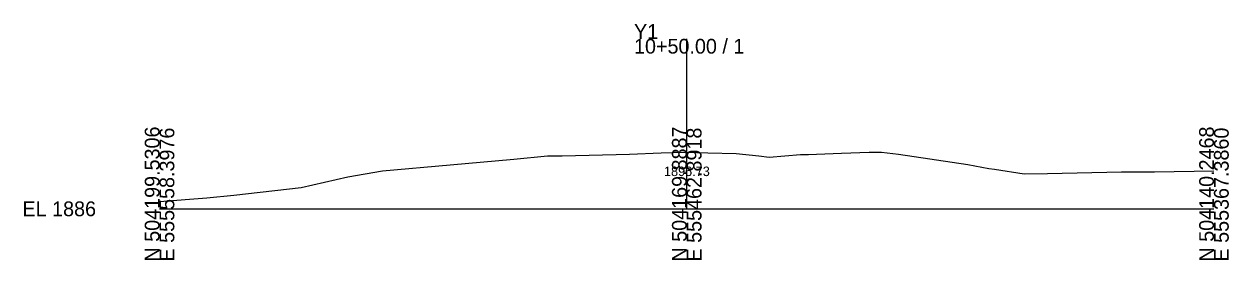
# Model space of a CAD drawing. Extents: x -26 to 1503, y -10 to 5015.
# Drawn here: x -25.7 to 202.8, y 490.3 to 535 of the extents above; entities that cross this region are included whole.
import ezdxf

# ---------------------------------------------------------------- set-up
doc = ezdxf.new("R2010")
doc.units = 0
for name, color, linetype in [('Default', 7, 'Continuous'), ('Exist Cross Section Cell', 7, 'Continuous'), ('Exist XS Center Line Elevation Label', 7, 'Continuous'), ('Exist XS Ground Line', 7, 'Continuous')]:
    doc.layers.add(name, color=color, linetype=linetype)

msp = doc.modelspace()

# ---------------------------------------------------------------- linework, layer by layer
at = {"layer": 'Exist Cross Section Cell'}
for p, q in [((100, 500), (100, 532.24)), ((0, 500), (100, 500)), ((100, 500), (200, 500))]:
    msp.add_line(p, q, dxfattribs=at)
at = {"layer": 'Exist XS Ground Line'}
for p, q in [((67.2, 509.39), (73.61, 510.05)), ((73.61, 510.05), (76.39, 510.05)), ((76.39, 510.05), (89.12, 510.37)), ((89.12, 510.37), (95.17, 510.6)), ((95.17, 510.6), (99.71, 510.74)), ((99.71, 510.74), (104.02, 510.61)), ((104.02, 510.61), (109.37, 510.46)), ((109.37, 510.46), (113.67, 510.08)), ((113.67, 510.08), (115.65, 509.8)), ((115.65, 509.8), (121.57, 510.32)), ((121.57, 510.32), (122.33, 510.32)), ((122.33, 510.32), (123.12, 510.33)), ((123.12, 510.33), (124.6, 510.37)), ((124.6, 510.37), (129.37, 510.55)), ((129.37, 510.55), (134.59, 510.72)), ((134.59, 510.72), (136.92, 510.75)), ((136.92, 510.75), (140.15, 510.37)), ((140.15, 510.37), (153.34, 508.38)), ((42.26, 507.2), (55.14, 508.34)), ((55.14, 508.34), (67.2, 509.39)), ((153.34, 508.38), (157.28, 507.66)), ((157.28, 507.66), (158.36, 507.52)), ((158.36, 507.52), (164.01, 506.66)), ((26.85, 504.05), (35.74, 506.06)), ((35.74, 506.06), (42.26, 507.2)), ((164.01, 506.66), (168.46, 506.69)), ((168.46, 506.69), (182.49, 507.04)), ((182.49, 507.04), (188.7, 507.01)), ((188.7, 507.01), (200, 507.22)), ((14.09, 502.58), (26.85, 504.05)), ((0, 501.41), (8.94, 502.1)), ((8.94, 502.1), (14.09, 502.58))]:
    msp.add_line(p, q, dxfattribs=at)

# ---------------------------------------------------------------- texts
at = {"layer": 'Default'}
msp.add_text('-', height=0.0001, dxfattribs=at).set_placement((0, 500))
at = {"layer": 'Exist Cross Section Cell'}
for s, p in [('Y1', (90, 532.24)), ('10+50.00 / 1', (90, 529.44)), ('EL 1886', (-26, 498.6))]:
    msp.add_text(s, height=2.8, dxfattribs=at).set_placement(p)
for s, p in [('N 504199.5306', (0, 490)), ('E 555558.3976', (2.8, 490)), ('N 504169.8887', (100, 490)), ('E 555462.8918', (102.8, 490)), ('N 504140.2468', (200, 490)), ('E 555367.3860', (202.8, 490))]:
    msp.add_text(s, height=2.8, rotation=90, dxfattribs=at).set_placement(p)
at = {"layer": 'Exist XS Center Line Elevation Label'}
msp.add_text('1896.73', height=1.8, dxfattribs=at).set_placement((95.68, 506.21))

doc.saveas('drawing.dxf')
